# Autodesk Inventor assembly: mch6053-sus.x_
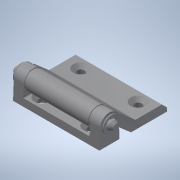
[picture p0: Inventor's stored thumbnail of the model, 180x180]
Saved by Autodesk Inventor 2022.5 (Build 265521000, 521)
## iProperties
Part Number: mch6053-sus.x_
Material: 一般
Document SubType Name: Assembly
Designer: ImaoCorp
Sending System: SOLIDWORKS 2017-2017317
MC: AMD64
MC_MODEL: Intel64 Family 6 Model 60 Stepping 3, GenuineIntel
OS: Windows_NT
FRU: Parasolid Version 29.0, build 201,  4-17-2017
FORMAT: text
GUISE: transmit
KEY: mch6053-sus
FILE: mch6053-sus.x_t
DATE: Fri Jul 26 11:41:30 2019
Author: ImaoCorp
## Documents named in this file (4)
- X:\14_SW2022-Inv2022\00_全2023-1023新製品(TCC)まで\m\mch6053-sus\MCH6053-SUS.iam
- X:\14_SW2022-Inv2022\00_全2023-1023新製品(TCC)まで\m\mch6053-sus\mch6053-sus_01.ipt
- X:\14_SW2022-Inv2022\00_全2023-1023新製品(TCC)まで\m\mch6053-sus\mch6053-sus_02.ipt
- X:\14_SW2022-Inv2022\00_全2023-1023新製品(TCC)まで\m\mch6053-sus\mch6053-sus_03.ipt
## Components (3 placed, 3 different names)
1. mch6053-sus_01
2. mch6053-sus_02
3. mch6053-sus_03
